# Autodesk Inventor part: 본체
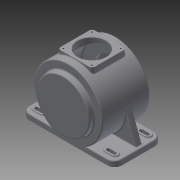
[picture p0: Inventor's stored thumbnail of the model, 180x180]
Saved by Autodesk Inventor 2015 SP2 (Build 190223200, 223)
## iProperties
Created: 2015-06
Part Number: 본체
Material: 일반
Document SubType Name: Modeling
Designer: Guest
Density: 1 g/cm^3
Appearance: 기본값
Author: Guest
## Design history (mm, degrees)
sketch "스케치1"
  geometry: L1 (-115, 59)-(115, 59); L2 (115, 59)-(115, -59); L3 (115, -59)-(-115, -59); L4 (-115, -59)-(-115, 59); 3 further points
  constraints: 8 end point, 2 midpoint, 2 parallel, 1 horizontal, 1 horizontal alignment, 1 perpendicular, 1 vertical alignment
  dimensions: "d0" = 230 distance of L1.start L1.end; "d1" = 118 distance of L3.end L1.start
extrude "돌출1" new body sketch "스케치1" distance "d2" = 14; taper "d3" = 0 deg
fillet "모깎기1" dims "d4" = 18
sketch "스케치2"
  geometry: L1 (115, 0)-(-115, 0) reference; L2 (-115, 0)-(-115, 14) reference; L3 (-115, 14)-(115, 14) reference; L4 (115, 14)-(115, 0) reference; C1 r 85 at (0, 85); 1 further point
  constraints: 1 centre point
  dimensions: "d5" = 170 diameter of C1; "d6" = 85 distance from line of L1 C1.centre
extrude "돌출2" join sketch "스케치2" stored distance "d7" = 118; taper "d8" = 0 deg
sketch "스케치4"
  geometry: C1 r 65 at (-97, 85); 1 further point
  constraints: 1 centre point
  dimensions: "d12" = 130 diameter of C1; "d13" = 85 distance of point (-97, 0) C1.centre
extrude "돌출3" join sketch "스케치4" distance "d14" = 13; taper "d15" = 0 deg
sketch "스케치7"
  geometry: C1 r 65 at (-97, -71); 6 further points
  constraints: 1 centre point, 1 coincident, 1 other
  dimensions: "d21" = 130 diameter of C1
extrude "돌출5" join sketch "스케치7" distance "d22" = 3; taper "d23" = 0 deg
sketch "스케치8"
  geometry: L1 (115, 0)-(-115, 0) reference; L2 (-115, 0)-(-115, 14) reference; L3 (-115, 14)-(-46.733, 14) reference; L4 (46.733, 14)-(115, 14) reference; L5 (115, 14)-(115, 0) reference; L6 (84.87, 80.297)-(109, 14); L7 (97, 14)-(115, 14) reference; A1 r 85 centre (0, 85) between (46.733, 14) and (-46.733, 14) reference; A2 r 85 centre (0, 85) between (46.733, 14) and (-46.733, 14) reference; 1 further point
  constraints: 2 end point, 2 point on circle, 1 point on line
  dimensions: "d33" = 6 distance of L4.end L6.end; "d34" = 110 deg angle of L6 L4
feature "리브1" sketch "스케치8" dims "d35" = 1, "d36" = 15, "d37" = 0, "d38" = 0, "d39" = 1, "d40" = 1
sketch "스케치9"
  geometry: L1 (115, 41)-(115, -41) reference; L2 (97, -59)-(46.733, -59) reference; L3 (46.733, 0)-(46.733, -59) reference; L4 (109, 0)-(46.733, 0) reference; L5 (109, 15)-(109, 0) reference; L6 (46.733, 15)-(109, 15) reference; L7 (46.733, 59)-(46.733, 15) reference; L8 (-46.733, 59)-(46.733, 59) reference; L9 (-46.733, 15)-(-46.733, 59) reference; L10 (-109, 15)-(-46.733, 15) reference; L11 (-109, 0)-(-109, 15) reference; L12 (-46.733, 0)-(-109, 0) reference; L13 (-46.733, -59)-(-46.733, 0) reference; L14 (-46.733, -59)-(-97, -59) reference; L15 (-115, -41)-(-115, 41) reference; L16 (-97, 59)-(-46.733, 59) reference; L17 (46.733, 59)-(97, 59) reference; L18 (46.733, -59)-(-46.733, -59) reference; L19 (-81, -49)-(-97, -49); L20 (-97, -33)-(-81, -33); A1 r 18 centre (97, -41) between (97, -59) and (115, -41) reference; A2 r 18 centre (-97, -41) between (-115, -41) and (-97, -59) reference; A3 r 18 centre (-97, 41) between (-97, 59) and (-115, 41) reference; A4 r 18 centre (97, 41) between (115, 41) and (97, 59) reference; A5 r 8 centre (-97, -41) between (-97, -33) and (-97, -49); A6 r 8 centre (-81, -41) between (-81, -49) and (-81, -33); 1 further point
  constraints: 4 end point, 4 point on circle, 4 tangent, 2 centre point
  dimensions: "d42" = 16 diameter of A5; "d44" = 16 diameter of A6
extrude "돌출6" join sketch "스케치9" distance "d46" = 3; taper "d47" = 0 deg
sketch "스케치10"
  geometry: L1 (-81, -49)-(-97, -49) reference; L2 (-97, -33)-(-81, -33) reference; L3 (-51, 15)-(-51, 59) reference; L4 (-51, 59)-(51, 59) reference; L5 (51, 59)-(51, 15) reference; L6 (51, 15)-(107.908, 15) reference; L7 (107.908, 15)-(107.908, 0) reference; L8 (107.908, 0)-(51, 0) reference; L9 (51, 0)-(51, -59) reference; L10 (51, -59)-(-51, -59) reference; L11 (-51, -59)-(-51, 0) reference; L12 (-51, 0)-(-107.908, 0) reference; L13 (-107.908, 0)-(-107.908, 15) reference; L14 (-107.908, 15)-(-51, 15) reference; L15 (-97, -45)-(-81, -45); L16 (-97, -37)-(-81, -37); A1 r 8 centre (-97, -41) between (-97, -33) and (-97, -49) reference; A2 r 8 centre (-81, -41) between (-81, -49) and (-81, -33) reference; A3 r 4 centre (-97, -41) between (-97, -37) and (-97, -45); A4 r 4 centre (-81, -41) between (-81, -45) and (-81, -37); 1 further point
  constraints: 4 end point, 4 point on circle, 2 centre point, 2 coincident, 2 tangent
  dimensions: "d48" = 8 diameter of A3; "d49" = 8 diameter of A4
extrude "돌출7" cut sketch "스케치10" stored distance "d50" = 3; taper "d51" = 0 deg
node "작업 평면3"
sketch "스케치11"
  geometry: L1 (42.5, -42.5)-(-42.5, -42.5); L2 (-42.5, -42.5)-(-42.5, 42.5); L3 (-42.5, 42.5)-(42.5, 42.5); L4 (42.5, 42.5)-(42.5, -42.5); 3 further points
  constraints: 8 end point, 2 midpoint, 2 parallel, 1 horizontal, 1 horizontal alignment, 1 perpendicular, 1 vertical alignment
  dimensions: "d52" = 85 distance of L1.start L1.end; "d53" = 85 distance of L3.end L1.start
extrude "돌출8" join sketch "스케치11" stored distance "d54" = 0; taper "d55" = 0 deg
sketch "스케치12"
  geometry: L1 (-42.5, 42.5)-(42.5, 42.5); L2 (42.5, 42.5)-(42.5, -42.5); L3 (42.5, -42.5)-(-42.5, -42.5); L4 (-42.5, -42.5)-(-42.5, 42.5); 1 further point
  constraints: 8 end point, 2 parallel, 1 horizontal, 1 perpendicular
extrude "돌출9" join sketch "스케치12" distance "d56" = 3; taper "d57" = 0 deg
sketch "스케치13"
  geometry: L1 (-72, 150)-(-59, 150) reference; L2 (-59, 150)-(-59, 170) reference; L3 (-59, 170)-(-42.5, 170) reference; L4 (-42.5, 170)-(-42.5, 173) reference; L5 (-42.5, 173)-(42.5, 173) reference; L6 (42.5, 173)-(42.5, 170) reference; L7 (42.5, 170)-(59, 170) reference; L8 (59, 170)-(59, 150) reference; L9 (59, 150)-(62, 150) reference; L10 (62, 150)-(62, 20) reference; L11 (62, 20)-(59, 20) reference; L12 (59, 20)-(59, 0) reference; L13 (59, 0)-(-59, 0) reference; L14 (-59, 0)-(-59, 20) reference; L15 (-59, 20)-(-72, 20) reference; L16 (-72, 20)-(-72, 150) reference; L17 (-72, 150)-(-72, 20) reference; L18 (-72, 85)-(62, 85); L19 (62, 20)-(62, 150) reference; L20 (62, 132.5)-(51, 132.5); L21 (51, 132.5)-(51, 162); L22 (51, 162)-(-51, 162); L23 (-51, 162)-(-51, 116); L24 (-51, 116)-(-47.5, 114.368); L25 (-47.5, 114.368)-(-47.5, 108.5); L26 (-47.5, 108.5)-(-61.5, 108.5); L27 (-61.5, 108.5)-(-61.5, 100); L28 (-61.5, 100)-(-64.5, 100); L29 (-64.5, 100)-(-64.5, 85); 1 further point
  constraints: 22 end point, 7 perpendicular, 2 midpoint, 2 point on line, 1 parallel
  dimensions: "d67" = 95 diameter of L20 L18; "d68" = 154 diameter of L22 L18; "d69" = 115 deg angle of L24 L23; "d70" = 3 distance between parallel lines of L27 L29; "d71" = 14 distance between parallel lines of L25 L27; "d72" = 102 distance of L21.end L22.end; "d74" = 3.5 distance from line of L23.end L25; "d75" = 62 diameter of L23.end L18; "d76" = 47 diameter of L26 L18; "d77" = 30 diameter of L28 L18
revolve "회전1" sketch "스케치13" stored, may be unused: angle "d78" = 90 deg
sketch "스케치14"
  geometry: C1 r 35 at (0, 0); 1 further point
  constraints: 1 centre point, 1 coincident
  dimensions: "d79" = 70 diameter of C1
extrude "돌출10" cut sketch "스케치14" stored distance "d80" = 3; taper "d81" = 0 deg
fillet "모깎기2" dims "d82" = 7
sketch "스케치15"
  geometry: L1 (-42.5, -35.5)-(-42.5, 35.5) reference; L2 (-35.5, -42.5)-(35.5, -42.5) reference; 2 further points
  dimensions: "d83" = 7 distance from line of L1 point (-35.5, -35.5); "d84" = 7 distance from line of L2 point (-35.5, -35.5)
hole "구멍3" sketch "스케치15" at (-35.5, -35.5) diameter "d85" = 3.242; stored, may be unused: countersink angle "d89" = 90 deg, drill point angle "d91" = 118 deg; dims "d86" = 10, "d87" = 95, "d88" = 11, "d90" = 13
fillet "모깎기3" dims "d95" = 3
fillet "모깎기4" dims "d96" = 3
fillet "모깎기5" dims "d97" = 2
fillet "모깎기6" dims "d98" = 3
fillet "모깎기7" dims "d99" = 3
fillet "모깎기8" dims "d100" = 3
sketch "스케치16"
  geometry: C1 r 65 at (0, 0) reference; C2 r 47.5 at (0, 0) reference; 2 further points
  constraints: 1 vertical alignment
  dimensions: "d101" = 55 distance of C1.centre point (0, -55)
hole "구멍4" sketch "스케치16" at (0, -55) diameter "d102" = 3.242; stored, may be unused: countersink angle "d106" = 90 deg, drill point angle "d108" = 118 deg; dims "d103" = 10, "d104" = 95, "d105" = 11, "d107" = 13
chamfer "모따기1" distance "d112" = 1; stored, may be unused: second distance "d113" = 2, angle "d114" = 45 deg
fillet "모깎기9" dims "d115" = 3
fillet "모깎기10" dims "d116" = 3
fillet "모깎기11" dims "d117" = 0.3
chamfer "모따기2" distance "d118" = 1; stored, may be unused: second distance "d119" = 2, angle "d120" = 45 deg
fillet "모깎기12" dims "d72" = 102, "d121" = 3
chamfer "모따기3" distance "d122" = 1; stored, may be unused: second distance "d123" = 2, angle "d124" = 45 deg
fillet "모깎기13" dims "d125" = 3
node "솔리드1"
mirror "대칭1"
mirror "대칭2"
mirror "대칭3"
pattern_circular "원형 패턴1" dims angle "d93" = 360 deg
pattern_circular "원형 패턴2" dims angle "d110" = 360 deg
node "절단 모서리 투영1"
node "절단 모서리 투영2"
node "절단 모서리 투영3"
node "절단 모서리 투영4"
node "절단 모서리 투영5"
node "절단 모서리 투영6"
